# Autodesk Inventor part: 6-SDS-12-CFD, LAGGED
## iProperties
Shininess: 50.0
Length Units: 11272
Angle Units: 11279
Time Units: 11290
Mass Units: 11286
Length Display Precision: 3
Angle Display Precision: 2
Manager: Cory McConnell
Company: MechaniX Design Solutions
Part Number: 6-SDS-12-CFD, LAGGED
Document SubType Name: Modeling
Designer: CM
Material: CSA G40.21 44W
Created: 2004-01
Manufacturer: Standard
Standards Organization: Custom
Description: LUFF® QD DRUM PULLEY
Density: 10.49
Volumn: 2.304646865681294
Area: 8.437628188859923
PropertySet Name: Model Information
Control State: 0
Master: False
Checked Out: False
PartAngTol0: 0.5 deg
PartAngTol1: 0.5 deg
PartAngTol2: 0.5 deg
PartAngTol3: 0.5 deg
PartAngTol4: 0.5 deg
PartLinTol1: 0.015 in
PartLinTol2: 0.01 in
PartLinTol3: 0.005 in
PartLinTol4: 0.001 in
Author: CM
Revision Number: 0
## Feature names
1. Revolution2
2. Revolution3
3. Hole4
4. Mirror1
5. Hole5
6. Circular Pattern2
7. Lagging [Revolution]
